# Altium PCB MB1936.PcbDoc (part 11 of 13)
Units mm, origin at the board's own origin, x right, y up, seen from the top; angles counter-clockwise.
Board outline 172 x 137 mm, 6 copper layers (Top Layer, Signal Layer 1, Signal Layer 2, Signal Layer 3, Signal Layer 4, Bottom Layer), stack 1.549 mm thick; 859 components, 672 nets, 3477 pads, 2222 vias.
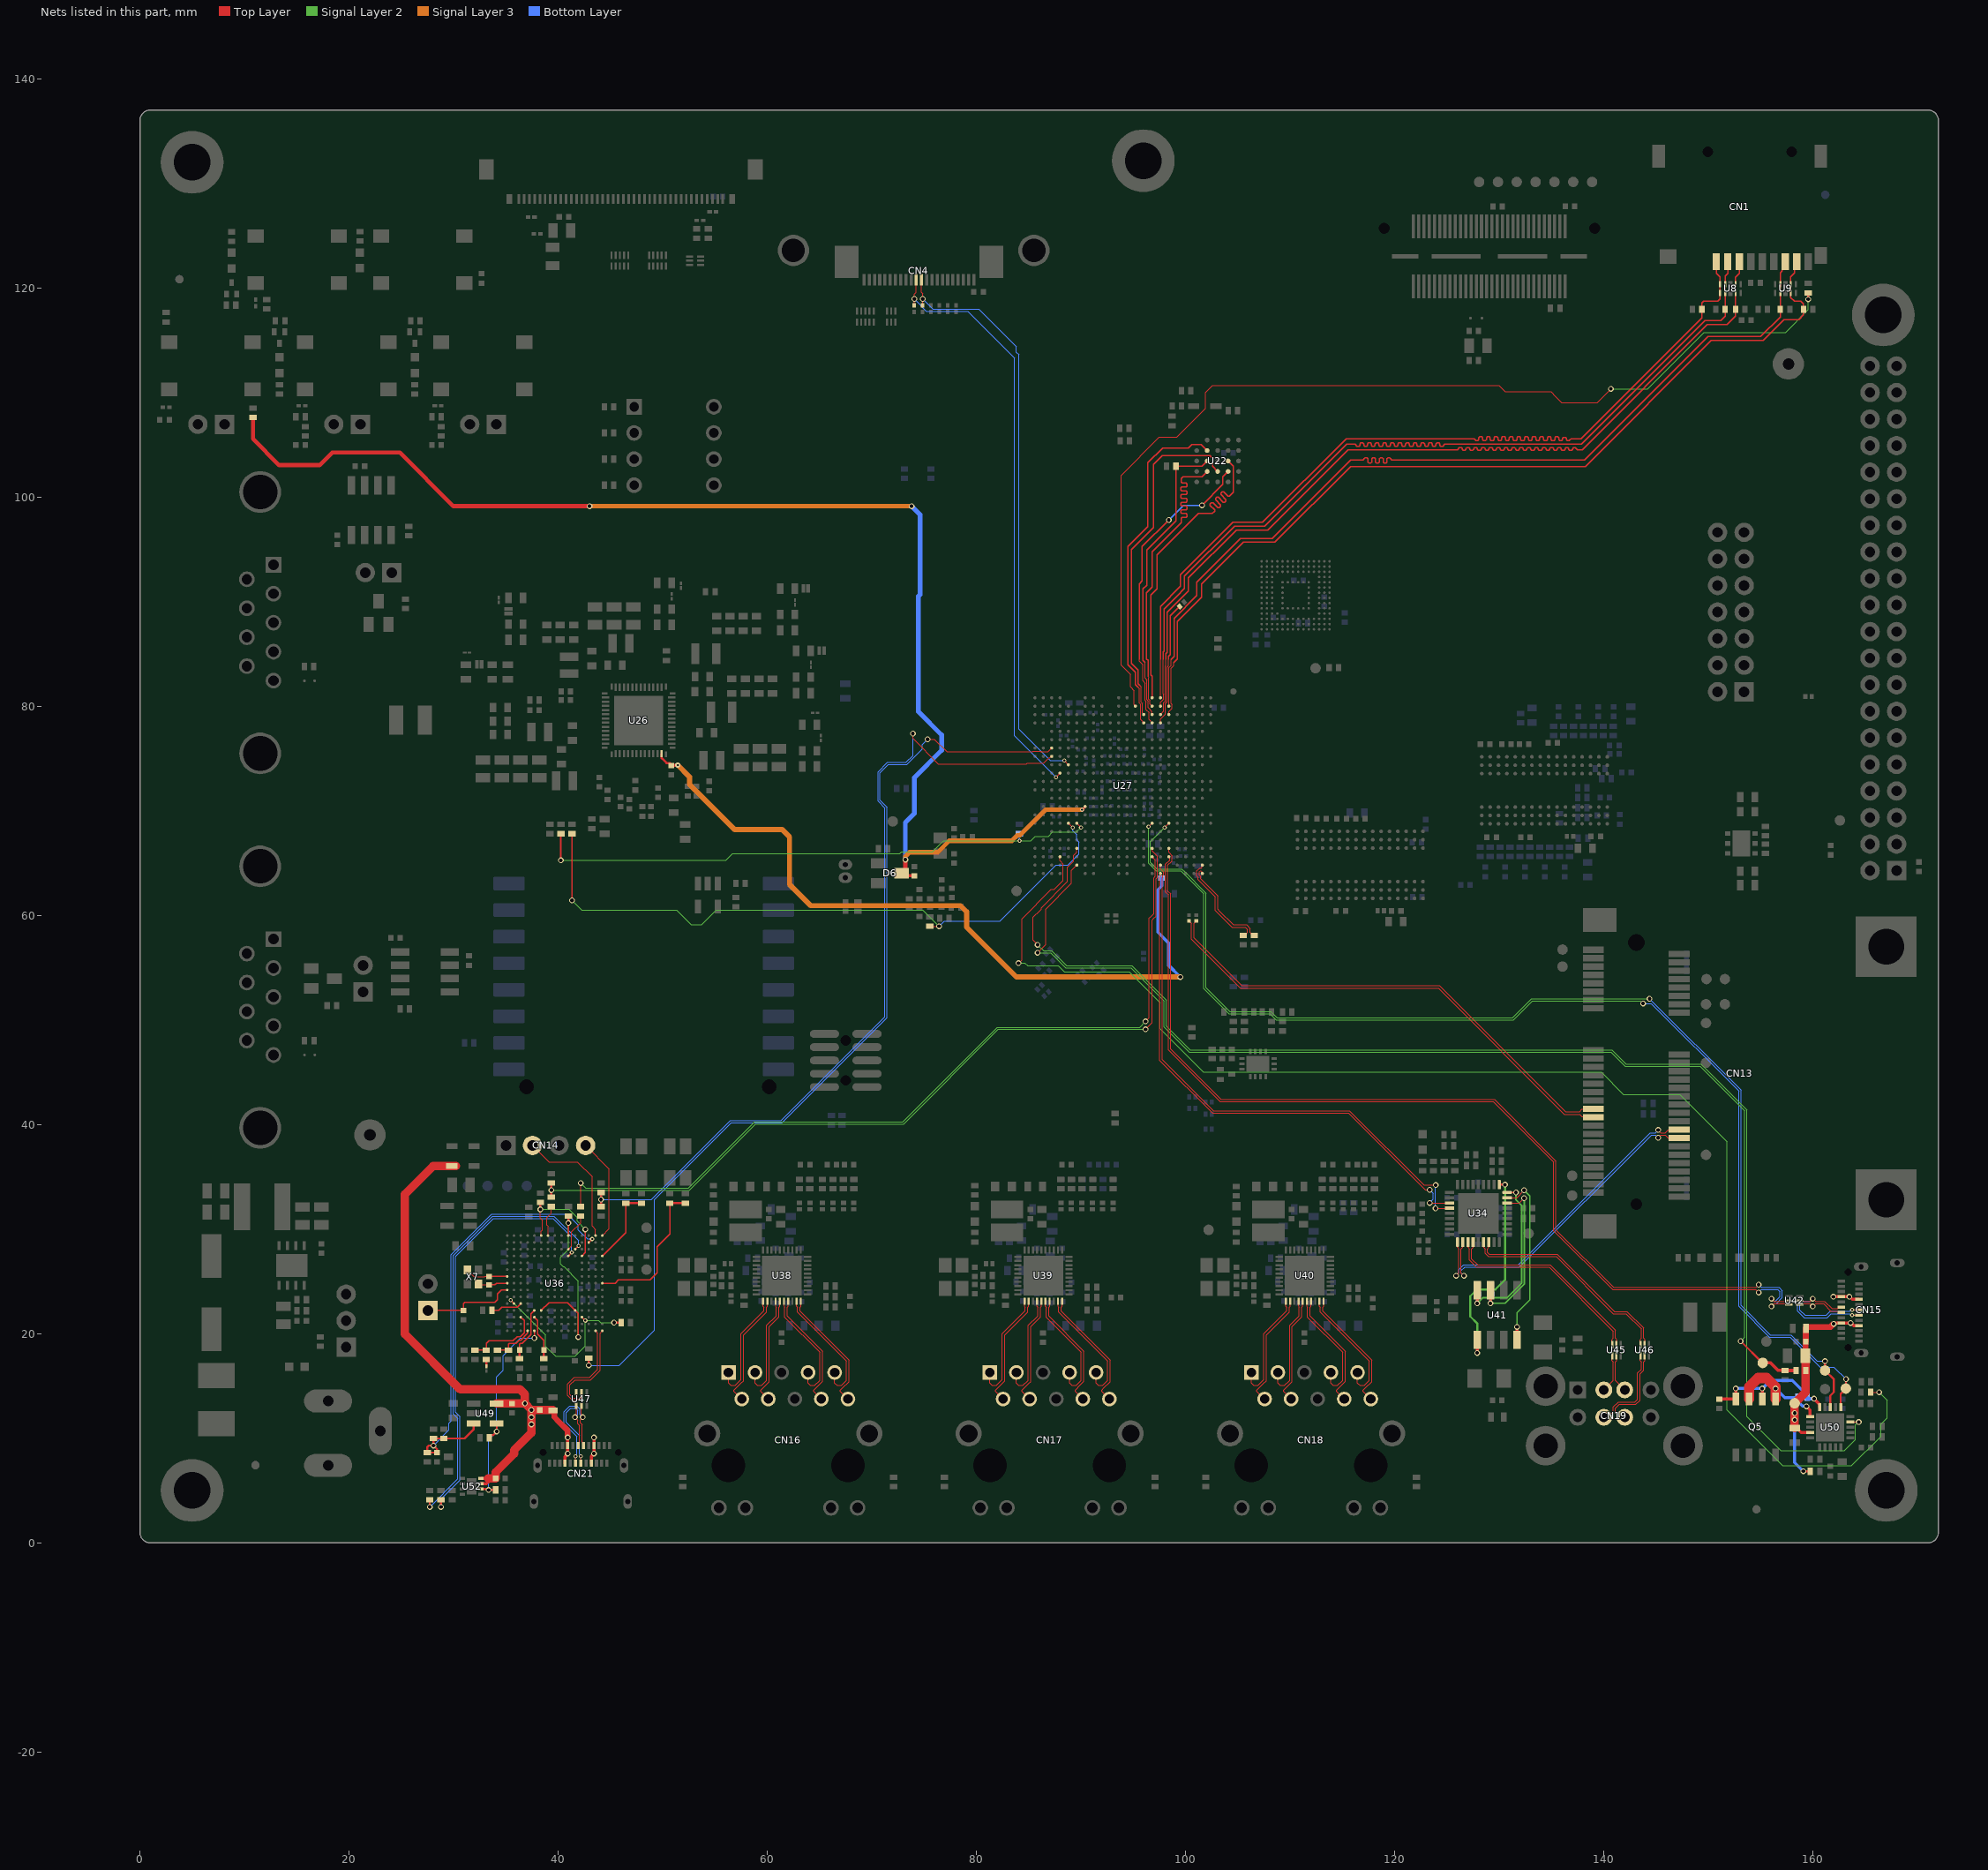
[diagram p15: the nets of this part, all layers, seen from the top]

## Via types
v1: diameter 0.55, hole 0.35, Top Layer to Bottom Layer, 1661 vias
v2: diameter 0.4, hole 0.2, Top Layer to Bottom Layer, tented both sides, 253 vias
v3: diameter 0.5, hole 0.2, Top Layer to Bottom Layer, 157 vias
v4: diameter 0.5, hole 0.25, Top Layer to Bottom Layer, 145 vias
v5: diameter 0.4, hole 0.2, Top Layer to Bottom Layer, 6 vias

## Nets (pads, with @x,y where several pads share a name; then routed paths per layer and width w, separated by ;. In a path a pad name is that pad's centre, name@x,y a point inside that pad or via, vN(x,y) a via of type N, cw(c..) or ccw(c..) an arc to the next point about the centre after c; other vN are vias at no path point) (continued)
PCIE.TX1_N: C98.2 CN13.31 | length 46.9
  Top Layer w0.09: C98.2@101.025,59.45 100.8,59.225 100.8,58.84 100.8,57.825 105.35,53.275 124.275,53.275 136.325,41.225 137.68,41.225 137.918,41.463 138.963,41.463 CN13.31@139,41.5
PCIE.TX1_P: C97.2 CN13.33 | length 47.3
  Top Layer w0.09: C97.2@100.325,59.45 100.55,59.225 100.55,58.84 100.55,57.721 105.246,53.025 124.171,53.025 136.221,40.975 137.68,40.975 137.918,40.737 138.963,40.737 CN13.33@139,40.7
PCIE.USB_N: CN13.36 U34.1 | length 30.9
  Top Layer w0.1: v1(125.875,25.543) 125.918,25.543 126.14,25.765 126.14,28.11 126,28.25 U34.1@126,28.75 ; v1(145.2,39.475) 145.2,39.455 145.445,39.21 145.86,39.21 146.15,39.5 CN13.36@147.2,39.5
  Bottom Layer w0.1: v1(125.875,25.543) 126.14,25.808 126.14,26.106 126.609,26.575 131.82,26.575 144.455,39.21 144.935,39.21 v1(145.2,39.475)
PCIE.USB_P: CN13.38 U34.2 | length 30.5
  Top Layer w0.1: U34.2@126.5,28.75 126.5,28.25 126.36,28.11 126.36,25.765 126.582,25.543 v1(126.625,25.543) ; v1(145.2,38.725) 145.2,38.745 145.445,38.99 145.86,38.99 146.15,38.7 CN13.38@147.2,38.7
  Bottom Layer w0.1: v1(126.625,25.543) 126.36,25.808 126.36,26.015 126.7,26.355 129.75,26.355 131.175,26.355 131.911,26.355 144.546,38.99 144.935,38.99 v1(145.2,38.725)
PCIE_CLKOUT_N: R78.1 U27.AB21 | length 9.6
  Top Layer w0.09: U27.AB21@101.6,64 101.56,64.04 101.56,64.195 101.504,64.251 101.425,64.251 101.335,64.16 101.335,63.85 101.445,63.74 101.445,63.509 102,62.954 102.85,62.104 103.082,61.872 103.082,60.571 103.179,60.475 104.554,59.1 105.825,59.1 106.175,58.75 106.175,58.475 106.175,58.333 106.224,58.285 106.365,58.285 R78.1@106.575,58.075
PCIE_CLKOUT_P: R77.1 U27.AA21 | length 10
  Top Layer w0.09: U27.AA21@101.6,64.8 101.56,64.76 101.56,64.585 101.5,64.525 101.346,64.525 101.085,64.264 101.085,63.746 101.195,63.637 101.195,63.543 101.195,63.406 101.75,62.85 102.6,62 102.832,61.768 102.832,60.475 102.832,60.468 104.45,58.85 105.721,58.85 105.925,58.646 105.925,58.35 105.925,58.333 105.877,58.285 105.735,58.285 R77.1@105.525,58.075
PWR_CPU_ON: R60.1 R272.2 U27.T6 | length 54.9
  Top Layer w0.1: U27.T6@89.6,68.8 v2(90,68.4)
  Top Layer w0.15: v1(40.25,65.25) 40.25,67.775 R60.1@40.275,67.8
  Signal Layer 2 w0.1: v1(40.25,65.25) 56.041,65.25 56.691,65.9 72.665,65.9 72.838,66.073 75.798,66.073 76.85,67.125 81.172,67.125 v2(84.125,67.125) 85.182,67.125 85.623,67.566 86.891,67.566 87.275,67.95 89.55,67.95 v2(90,68.4)
  Bottom Layer w0.1: R272.2@84.1,67.8 84.125,67.775 v2(84.125,67.125)
PWR_ON: R61.1 R74.2 U27.T5 | length 64.1
  Top Layer w0.09: R74.2@75.55,58.95 v1(76.425,58.95)
  Top Layer w0.1: U27.T5@88.8,68.8 v2(89.2,68.4)
  Top Layer w0.15: v1(41.325,61.425) R61.1@41.325,67.8
  Signal Layer 2 w0.1: v1(41.325,61.425) 42.25,60.5 51.325,60.5 52.725,59.1 53.725,59.1 55.125,60.5 74.875,60.5 v1(76.425,58.95)
  Bottom Layer w0.1: v1(76.425,58.95) 76.925,59.45 82.251,59.45 83.276,60.475 87.601,64.8 88.761,64.8 89.805,65.844 89.805,67.006 89.6,67.211 89.6,67.696 89.2,68.095 v2(89.2,68.4)
QSPI1.CLK: U22.B2 U27.D14 | length 32.9
  Top Layer w0.09: 95.44,81.81 95.585,81.665 95.585,80.308 95.69,80.203 95.69,78.71 U27.D14@96,78.4
  Top Layer w0.11: 95.44,81.81 95.2,82.05 95.2,83.25 94.475,83.975 94.475,95.25 96.4,97.175 96.4,103.275 97.8,104.675 100.25,104.675 100.6,105.025 101.482,105.025 U22.B2@102.066,104.441
QSPI1.IO0: U22.D3 U27.C14 | length 32.8
  Top Layer w0.09: 95.63,81.97 95.765,81.835 95.765,80.383 95.87,80.278 95.87,79.361 96,79.231 U27.C14@96,79.2
  Top Layer w0.11: 95.63,81.97 95.45,82.15 95.45,83.468 94.825,84.093 94.825,84.475 94.825,94.975 96.925,97.075 96.925,103.107 97.768,103.95 102.35,103.95 102.575,103.725 102.575,102.932 U22.D3@103.066,102.441
QSPI1.IO1: U22.D2 U27.B15 | length 31
  Top Layer w0.09: 96.405,82.82 96.485,82.74 96.485,80.681 96.59,80.576 96.59,80.225 96.8,80.015 U27.B15@96.8,80
  Top Layer w0.11: 96.405,82.82 96.405,84.395 96.271,84.529 96.271,90.846 96.825,91.4 96.825,94.775 99.575,97.525 99.575,97.54 99.575,97.959 99.666,98.05 100.064,98.05 100.155,98.141 100.155,98.323 100.064,98.414 99.645,98.414 99.554,98.505 99.554,98.687 99.645,98.778 100.064,98.778 100.155,98.869 100.155,99.051 100.064,99.142 99.645,99.142 99.554,99.233 99.554,99.415 99.645,99.506 100.064,99.506 100.155,99.597 100.155,99.779 100.064,99.87 99.645,99.87 99.554,99.961 99.554,100.143 99.645,100.234 100.064,100.234 100.155,100.325 100.155,100.507 100.064,100.598 99.645,100.598 99.554,100.689 99.554,100.871 99.645,100.962 100.064,100.962 100.155,101.053 100.155,101.235 100.064,101.326 99.666,101.326 99.575,101.417 99.575,101.55 99.575,101.75 99.775,101.95 101.575,101.95 U22.D2@102.066,102.441
QSPI1.IO2: U22.C4 U27.A15 | length 31.3
  Top Layer w0.11: U27.A15@96.8,80.8 96.8,82.85 96.68,82.97 96.68,90.63 97.275,91.225 97.275,94.45 101.25,98.425 102.55,98.425 102.737,98.612 102.776,98.651 102.776,98.78 102.351,99.206 102.351,99.334 102.479,99.463 102.608,99.463 103.083,98.988 103.212,98.988 103.34,99.117 103.34,99.246 102.866,99.721 102.866,99.849 102.994,99.978 103.123,99.978 103.598,99.503 103.726,99.503 103.855,99.632 103.855,99.761 103.38,100.235 103.38,100.364 103.509,100.493 103.638,100.493 104.063,100.067 104.192,100.067 104.563,100.438 104.575,100.45 104.575,102.932 U22.C4@104.066,103.441
QSPI1.IO3: U22.D4 U27.D15 | length 29.1
  Top Layer w0.09: 95.9,82.425 96.125,82.2 96.125,80.532 96.23,80.427 96.23,79.663 96.49,79.403 96.49,78.8 96.49,78.71 U27.D15@96.8,78.4
  Top Layer w0.1: 95.575,84.475 95.575,84.3 95.9,83.975 95.9,82.425
  Top Layer w0.11: 95.575,84.475 95.575,91.689 95.85,91.964 95.85,95.25 v1@98.399,97.799 ; v1(101.575,99.2) 103.575,101.2 103.575,101.95 U22.D4@104.066,102.441
  Bottom Layer w0.11: v1(98.4,97.8) 99.8,99.2 v1(101.575,99.2)
QSPI1.NCS1: R33.1 U22.C2 U27.C15 | length 28.6
  Top Layer w0.09: 96.125,82.675 96.305,82.495 96.305,80.606 96.41,80.501 96.41,79.866 96.781,79.495 96.781,79.219 U27.C15@96.8,79.2
  Top Layer w0.1: 96.125,82.675 96.125,84.18
  Top Layer w0.11: 96.125,84.18 95.925,84.38 95.925,84.641 95.925,91.2 96.3,91.575 96.3,94.925 99.084,97.709 R33.1@99.084,102.95 101.575,102.95 U22.C2@102.066,103.441
RJ451_D1_N: CN17.2 U39.2 | length 11
  Top Layer w0.09: CN17.2@82.555,13.75 81.825,14.48 81.825,14.6 82.369,15.144 82.496,15.271 82.725,15.5 82.725,19.875 84.925,22.075 84.925,22.55 85,22.625 U39.2@85,23.1
RJ451_D1_P: CN17.1 U39.1 | length 11
  Top Layer w0.09: CN17.1@81.285,16.29 81.285,15.265 81.5,15.05 81.921,15.05 82.392,15.521 82.475,15.604 82.475,19.979 84.675,22.179 84.675,22.55 84.6,22.625 U39.1@84.6,23.1
RJ451_D2_N: CN17.4 U39.5 | length 10.4
  Top Layer w0.09: CN17.4@85.095,13.75 84.365,14.48 84.365,14.6 84.909,15.144 85.036,15.271 85.182,15.417 85.2,15.435 85.2,20.675 86.125,21.6 86.125,22.55 86.2,22.625 U39.5@86.2,23.1
RJ451_D2_P: CN17.3 U39.4 | length 10.4
  Top Layer w0.09: CN17.3@83.825,16.29 83.825,15.265 84.04,15.05 84.461,15.05 84.95,15.539 84.95,20.779 85.875,21.704 85.875,22.55 85.8,22.625 U39.4@85.8,23.1
RJ451_D3_N: CN17.8 U39.7 | length 11.4
  Top Layer w0.09: U39.7@87,23.1 87,22.625 86.925,22.55 86.925,21.679 90.275,18.329 90.275,15.43 89.989,15.144 89.445,14.6 89.445,14.48 CN17.8@90.175,13.75
RJ451_D3_P: CN17.7 U39.6 | length 11.4
  Top Layer w0.09: U39.6@86.6,23.1 86.6,22.625 86.675,22.55 86.675,21.575 90.025,18.225 90.025,15.534 89.541,15.05 89.12,15.05 88.905,15.265 CN17.7@88.905,16.29
RJ451_D4_N: CN17.10 U39.10 | length 12
  Top Layer w0.09: U39.10@88.2,23.1 88.2,22.625 88.125,22.55 88.125,22.154 91.625,18.654 92.802,17.476 92.802,15.417 92.221,14.836 91.985,14.6 91.985,14.48 CN17.10@92.715,13.75
RJ451_D4_P: CN17.9 U39.9 | length 12
  Top Layer w0.09: U39.9@87.8,23.1 87.8,22.625 87.875,22.55 87.875,22.05 92.552,17.373 92.552,15.521 92.081,15.05 91.66,15.05 91.445,15.265 CN17.9@91.445,16.29
RJ452_D1_N: CN16.2 U38.2 | length 11
  Top Layer w0.09: CN16.2@57.555,13.75 56.825,14.48 56.825,14.6 57.369,15.144 57.496,15.271 57.725,15.5 57.725,19.875 59.925,22.075 59.925,22.55 60,22.625 U38.2@60,23.1
RJ452_D1_P: CN16.1 U38.1 | length 11
  Top Layer w0.09: CN16.1@56.285,16.29 56.285,15.265 56.5,15.05 56.921,15.05 57.392,15.521 57.475,15.604 57.475,19.979 59.675,22.179 59.675,22.55 59.6,22.625 U38.1@59.6,23.1
RJ452_D2_N: CN16.4 U38.5 | length 10.4
  Top Layer w0.09: CN16.4@60.095,13.75 59.365,14.48 59.365,14.6 59.909,15.144 60.036,15.271 60.182,15.417 60.2,15.435 60.2,20.675 61.125,21.6 61.125,22.55 61.2,22.625 U38.5@61.2,23.1
RJ452_D2_P: CN16.3 U38.4 | length 10.4
  Top Layer w0.09: CN16.3@58.825,16.29 58.825,15.265 59.04,15.05 59.461,15.05 59.95,15.539 59.95,20.779 60.875,21.704 60.875,22.55 60.8,22.625 U38.4@60.8,23.1
RJ452_D3_N: CN16.8 U38.7 | length 11.4
  Top Layer w0.09: U38.7@62,23.1 62,22.625 61.925,22.55 61.925,21.679 65.275,18.329 65.275,15.43 64.989,15.144 64.445,14.6 64.445,14.48 CN16.8@65.175,13.75
RJ452_D3_P: CN16.7 U38.6 | length 11.4
  Top Layer w0.09: U38.6@61.6,23.1 61.6,22.625 61.675,22.55 61.675,21.575 65.025,18.225 65.025,15.534 64.541,15.05 64.12,15.05 63.905,15.265 CN16.7@63.905,16.29
RJ452_D4_N: CN16.10 U38.10 | length 12
  Top Layer w0.09: U38.10@63.2,23.1 63.2,22.625 63.125,22.55 63.125,22.154 66.625,18.654 67.802,17.476 67.802,15.417 67.221,14.836 66.985,14.6 66.985,14.48 CN16.10@67.715,13.75
RJ452_D4_P: CN16.9 U38.9 | length 12
  Top Layer w0.09: U38.9@62.8,23.1 62.8,22.625 62.875,22.55 62.875,22.05 67.552,17.373 67.552,15.521 67.081,15.05 66.66,15.05 66.445,15.265 CN16.9@66.445,16.29
RJ453_D1_N: CN18.2 U40.2 | length 11
  Top Layer w0.09: CN18.2@107.555,13.75 106.825,14.48 106.825,14.6 107.369,15.144 107.496,15.271 107.725,15.5 107.725,19.875 109.925,22.075 109.925,22.55 110,22.625 U40.2@110,23.1
RJ453_D1_P: CN18.1 U40.1 | length 11
  Top Layer w0.09: CN18.1@106.285,16.29 106.285,15.265 106.5,15.05 106.921,15.05 107.392,15.521 107.475,15.604 107.475,19.979 109.675,22.179 109.675,22.55 109.6,22.625 U40.1@109.6,23.1
RJ453_D2_N: CN18.4 U40.5 | length 10.4
  Top Layer w0.09: CN18.4@110.095,13.75 109.365,14.48 109.365,14.6 109.909,15.144 110.036,15.271 110.182,15.417 110.2,15.435 110.2,20.675 111.125,21.6 111.125,22.55 111.2,22.625 U40.5@111.2,23.1
RJ453_D2_P: CN18.3 U40.4 | length 10.4
  Top Layer w0.09: CN18.3@108.825,16.29 108.825,15.265 109.04,15.05 109.461,15.05 109.95,15.539 109.95,20.779 110.875,21.704 110.875,22.55 110.8,22.625 U40.4@110.8,23.1
RJ453_D3_N: CN18.8 U40.7 | length 11.4
  Top Layer w0.09: U40.7@112,23.1 112,22.625 111.925,22.55 111.925,21.679 115.275,18.329 115.275,15.43 114.989,15.144 114.445,14.6 114.445,14.48 CN18.8@115.175,13.75
RJ453_D3_P: CN18.7 U40.6 | length 11.4
  Top Layer w0.09: U40.6@111.6,23.1 111.6,22.625 111.675,22.55 111.675,21.575 115.025,18.225 115.025,15.534 114.541,15.05 114.12,15.05 113.905,15.265 CN18.7@113.905,16.29
RJ453_D4_N: CN18.10 U40.10 | length 12
  Top Layer w0.09: U40.10@113.2,23.1 113.2,22.625 113.125,22.55 113.125,22.154 116.625,18.654 117.802,17.476 117.802,15.417 117.221,14.836 116.985,14.6 116.985,14.48 CN18.10@117.715,13.75
RJ453_D4_P: CN18.9 U40.9 | length 12
  Top Layer w0.09: U40.9@112.8,23.1 112.8,22.625 112.875,22.55 112.875,22.05 117.552,17.373 117.552,15.521 117.081,15.05 116.66,15.05 116.445,15.265 CN18.9@116.445,16.29
SD.SDMMC1_CK: R247.1 U27.D16 | length 11.9
  Top Layer w0.09: 97.6,78.762 98.09,79.252 98.09,80.244 98.245,80.399 98.245,83.761 98.369,83.885 98.369,84.475
  Top Layer w0.1: U27.D16@97.6,78.4 97.6,78.762
  Top Layer w0.11: 98.369,84.475 98.369,84.744 98.55,84.925 98.55,88.65 R247.1@99.438,89.538
SD.SDMMC1_CMD: CN1.3 R12.1 U8.4 U8.7 U27.C16 | length 86.1
  Top Layer w0.09: U27.C16@97.6,79.2 97.91,79.51 97.91,80.319 98.065,80.474 98.065,83.836 98.115,83.886 98.115,84.475
  Top Layer w0.11: 98.115,84.475 98.115,85.015 98.237,85.138 98.237,88.962 100.285,91.01 100.285,92.26 104.846,96.82 107.845,96.82 115.525,104.5 125.946,104.5 126.001,104.5 126.092,104.591 126.092,104.614 126.183,104.705 126.365,104.705 126.456,104.614 126.456,104.567 126.547,104.476 126.729,104.476 126.82,104.567 126.82,104.614 126.911,104.705 127.093,104.705 127.184,104.614 127.184,104.567 127.275,104.476 127.457,104.476 127.548,104.567 127.548,104.614 127.639,104.705 127.821,104.705 127.912,104.614 127.912,104.567 128.003,104.476 128.185,104.476 128.276,104.567 128.276,104.614 128.367,104.705 128.549,104.705 128.64,104.614 128.64,104.567 128.731,104.476 128.913,104.476 129.004,104.567 129.004,104.614 129.095,104.705 129.277,104.705 129.368,104.614 129.368,104.567 129.459,104.476 129.641,104.476 129.732,104.567 129.732,104.614 129.823,104.705 130.005,104.705 130.096,104.614 130.096,104.567 130.187,104.476 130.369,104.476 130.46,104.567 130.46,104.614 130.551,104.705 130.733,104.705 130.824,104.614 130.824,104.567 130.915,104.476 131.097,104.476 131.188,104.567 131.188,104.614 131.279,104.705 131.461,104.705 131.552,104.614 131.552,104.567 131.643,104.476 131.825,104.476 131.916,104.567 131.916,104.614 132.007,104.705 132.189,104.705 132.28,104.614 132.28,104.567 132.371,104.476 132.553,104.476 132.644,104.567 132.644,104.614 132.735,104.705 132.917,104.705 133.008,104.614 133.008,104.567 133.099,104.476 133.281,104.476 133.372,104.567 133.372,104.614 133.463,104.705 133.645,104.705 133.736,104.614 133.736,104.567 133.827,104.476 134.009,104.476 134.1,104.567 134.1,104.614 134.191,104.705 134.373,104.705 134.464,104.614 134.464,104.567 134.555,104.476 134.737,104.476 134.828,104.567 134.828,104.614 134.919,104.705 135.101,104.705 135.192,104.614 135.192,104.567 135.283,104.476 135.465,104.476 135.556,104.567 135.556,104.614 135.647,104.705 135.829,104.705 135.92,104.614 135.92,104.567 136.011,104.476 136.193,104.476 136.284,104.567 136.284,104.614 136.375,104.705 136.557,104.705 136.648,104.614 136.648,104.567 136.739,104.476 136.921,104.476 137.012,104.567 137.012,104.611 137.103,104.702 137.285,104.702 137.376,104.611 137.376,104.591 137.467,104.5 137.7,104.5 137.925,104.5 149.9,116.475 151.8,116.475 152.6,117.275 R12.1@152.6,117.95 U8.4@152.6,119.52 U8.7@152.6,120.34 152.6,121.02 152.95,121.37 CN1.3@152.95,122.5
SD.SDMMC1_D0: CN1.7 R14.1 U9.2 U9.9 U27.B17 | length 87.4
  Top Layer w0.09: U27.B17@98.4,80 98.4,80.3 98.425,80.325 98.425,83.687 98.623,83.885 98.623,84.473
  Top Layer w0.11: 98.625,84.475 98.9,84.75 98.9,88.4 101.081,90.581 101.081,91.856 105.25,96.025 108.3,96.025 115.8,103.525 116.913,103.525 116.968,103.525 117.077,103.634 117.077,103.649 117.186,103.758 117.332,103.758 117.441,103.649 117.441,103.331 117.55,103.222 117.696,103.222 117.805,103.331 117.805,103.649 117.914,103.758 118.06,103.758 118.169,103.649 118.169,103.331 118.278,103.222 118.424,103.222 118.533,103.331 118.533,103.649 118.642,103.758 118.788,103.758 118.897,103.649 118.897,103.331 119.006,103.222 119.152,103.222 119.261,103.331 119.261,103.649 119.37,103.758 119.516,103.758 119.625,103.649 119.625,103.634 119.734,103.525 120.062,103.525 138.15,103.525 149.975,115.35 155.005,115.35 156.875,117.22 R14.1@156.875,117.95 U9.2@156.875,119.52 U9.9@156.875,120.34 156.875,121.425 157.068,121.618 157.068,122.218 CN1.7@157.35,122.5
SD.SDMMC1_D1: CN1.8 R15.1 U9.4 U9.7 U27.C17 | length 88.3
  Top Layer w0.09: U27.C17@98.4,79.2 98.4,79.5 98.685,79.785 98.685,80.156 98.605,80.236 98.605,83.612 98.877,83.884 98.877,84.18
  Top Layer w0.11: 98.877,84.18 99.225,84.527 99.225,88.1 101.525,90.4 101.525,91.675 105.55,95.7 108.55,95.7 115.775,102.925 138.225,102.925 150.275,114.975 155.25,114.975 157.225,116.95 158.65,116.95 159.1,117.4 R15.1@159.1,117.95 159.1,118.47 158.845,118.725 158.225,118.725 157.875,119.075 U9.4@157.875,119.52 U9.7@157.875,120.34 157.875,121.045 158.25,121.42 158.25,122.3 CN1.8@158.45,122.5
SD.SDMMC1_D2: CN1.1 R10.1 U8.1 U8.10 U27.A16 | length 86.1
  Top Layer w0.09: U27.A16@97.6,80.8 97.6,84.475
  Top Layer w0.11: 97.6,84.475 97.6,89.525 99.525,91.45 99.525,92.575 104.531,97.581 107.356,97.581 115.35,105.575 127.17,105.575 127.589,105.575 127.68,105.484 127.68,105.471 127.771,105.38 127.953,105.38 128.044,105.471 128.044,105.665 128.135,105.756 128.317,105.756 128.408,105.665 128.408,105.471 128.499,105.38 128.681,105.38 128.772,105.471 128.772,105.665 128.863,105.756 129.045,105.756 129.136,105.665 129.136,105.471 129.227,105.38 129.409,105.38 129.5,105.471 129.5,105.665 129.591,105.756 129.773,105.756 129.864,105.665 129.864,105.471 129.955,105.38 130.137,105.38 130.228,105.471 130.228,105.665 130.319,105.756 130.501,105.756 130.592,105.665 130.592,105.471 130.683,105.38 130.865,105.38 130.956,105.471 130.956,105.665 131.047,105.756 131.229,105.756 131.32,105.665 131.32,105.471 131.411,105.38 131.593,105.38 131.684,105.471 131.684,105.665 131.775,105.756 131.957,105.756 132.048,105.665 132.048,105.471 132.139,105.38 132.321,105.38 132.412,105.471 132.412,105.665 132.503,105.756 132.685,105.756 132.776,105.665 132.776,105.471 132.867,105.38 133.049,105.38 133.14,105.471 133.14,105.665 133.231,105.756 133.413,105.756 133.504,105.665 133.504,105.471 133.595,105.38 133.777,105.38 133.868,105.471 133.868,105.665 133.959,105.756 134.141,105.756 134.232,105.665 134.232,105.471 134.323,105.38 134.505,105.38 134.596,105.471 134.596,105.665 134.687,105.756 134.869,105.756 134.96,105.665 134.96,105.471 135.051,105.38 135.233,105.38 135.324,105.471 135.324,105.665 135.415,105.756 135.597,105.756 135.688,105.665 135.688,105.471 135.779,105.38 135.961,105.38 136.052,105.471 136.052,105.588 136.143,105.679 136.325,105.679 136.416,105.588 136.416,105.484 136.507,105.393 136.689,105.393 136.78,105.484 136.871,105.575 137.65,105.575 137.825,105.575 149.375,117.125 R10.1@149.375,117.95 149.375,118.55 149.55,118.725 150.885,118.725 151.1,118.94 U8.1@151.1,119.52 U8.10@151.1,120.34 151.1,121.04 150.75,121.39 CN1.1@150.75,122.5
SD.SDMMC1_D3: CN1.2 R11.1 U8.2 U8.9 U27.B16 | length 86.1
  Top Layer w0.09: U27.B16@97.6,80 97.6,80.365 97.805,80.57 97.805,80.574 97.885,80.654 97.885,81.151 97.861,81.175 97.861,84.475
  Top Layer w0.11: 97.861,84.475 97.861,85.186 97.938,85.262 97.938,89.284 99.15,90.496 99.896,91.242 99.896,92.421 104.684,97.209 107.584,97.209 115.425,105.05 115.8,105.05 116.219,105.05 116.31,104.959 116.31,104.917 116.401,104.826 116.583,104.826 116.674,104.917 116.674,105.074 116.765,105.165 116.947,105.165 117.038,105.074 117.038,104.917 117.129,104.826 117.311,104.826 117.402,104.917 117.402,105.074 117.493,105.165 117.675,105.165 117.766,105.074 117.766,104.917 117.857,104.826 118.039,104.826 118.13,104.917 118.13,105.074 118.221,105.165 118.403,105.165 118.494,105.074 118.494,104.917 118.585,104.826 118.767,104.826 118.858,104.917 118.858,105.074 118.949,105.165 119.131,105.165 119.222,105.074 119.222,104.917 119.313,104.826 119.495,104.826 119.586,104.917 119.586,105.074 119.677,105.165 119.859,105.165 119.95,105.074 119.95,104.917 120.041,104.826 120.223,104.826 120.314,104.917 120.314,105.074 120.405,105.165 120.587,105.165 120.678,105.074 120.678,104.917 120.769,104.826 120.951,104.826 121.042,104.917 121.042,105.074 121.133,105.165 121.315,105.165 121.406,105.074 121.406,104.917 121.497,104.826 121.679,104.826 121.77,104.917 121.77,105.074 121.861,105.165 122.043,105.165 122.134,105.074 122.134,104.917 122.225,104.826 122.407,104.826 122.498,104.917 122.498,105.074 122.589,105.165 122.771,105.165 122.862,105.074 122.862,104.917 122.953,104.826 123.135,104.826 123.226,104.917 123.226,105.074 123.317,105.165 123.499,105.165 123.59,105.074 123.59,104.917 123.681,104.826 123.863,104.826 123.954,104.917 123.954,105.074 124.045,105.165 124.227,105.165 124.318,105.074 124.318,104.928 124.409,104.837 124.591,104.837 124.682,104.928 124.682,104.959 124.773,105.05 125.7,105.05 137.85,105.05 149.675,116.875 151.2,116.875 151.6,117.275 R11.1@151.6,117.95 U8.2@151.6,119.52 U8.9@151.6,120.34 151.6,121.128 151.85,121.378 CN1.2@151.85,122.5
SD.uSD_DETECT: R6.1 U27.B13 | length 98.8
  Top Layer w0.09: 93.85,84.475 93.85,83.92 94.745,83.025 94.745,81.835 95.095,81.485 95.095,80.158 95.2,80.053 U27.B13@95.2,80
  Top Layer w0.1: 93.85,84.475 93.85,102.078 97.497,105.725 99.165,105.725 101.9,108.46 101.9,110 102.575,110.675 129.96,110.675 130.575,110.06 134.929,110.06 135.378,109.611 ; 135.371,109.604 135.94,109.035 139.36,109.035 v1(140.675,110.35)
  Top Layer w0.2: v1(159.55,118.905) R6.1@159.55,119.525
  Signal Layer 2 w0.1: v1(140.675,110.35) 144.2,110.35 149.6,115.75 157.375,115.75 159.55,117.925 v1(159.55,118.905)
SRC_GDPG: C162.1 Q5.2 Q5.4 R325.2 U50.5 | length 13.2
  Top Layer w0.2: Q5.2@155.15,13.755 Q5.2@155.155,13.75
  Top Layer w0.3: C162.1@151.045,13.75 Q5.4@152.615,13.75 ; Q5.4@152.61,13.755 v1(152.61,14.75) ; Q5.2@155.15,13.755 v1(155.15,14.75) ; v1(160.1,13.775) 160.65,13.225 U50.5@160.65,12.975
  Bottom Layer w0.3: v1(152.61,14.75) v1(155.15,14.75) 155.925,15.525 158.025,15.525 159.345,14.205 159.345,14.03 R325.2@159.45,13.925 ; R325.2@159.401,13.775 v1(160.1,13.775)
SRC_GDPS: Q5.1 Q5.3 R325.1 U50.6 | length 11.6
  Top Layer w0.3: Q5.1@156.42,13.755 v1(156.42,14.75) ; v1(159.375,13.05) 159.725,12.7 U50.6@159.725,12.05
  Top Layer w1: Q5.3@153.885,13.75 153.885,14.9 154.741,15.756 155.569,15.756 156.425,14.9 Q5.1@156.425,13.75
  Bottom Layer w0.3: v1(156.42,14.75) 157.295,13.875 R325.1@158.55,13.875 ; R325.1@158.55,13.925 158.655,13.82 158.655,13.41 158.982,13.082 159.343,13.082 v1(159.375,13.05)
STLK_LED: R130.1 R131.2 U36.D15 | length 7.5
  Top Layer w0.12: U36.D15@44.225,27.425 46.475,29.675 R130.1@46.475,32.475
  Top Layer w0.2: R130.1@46.475,32.475 R131.2@47.975,32.475
STLK_NRST: C149.2 JP3.1 U36.J1 | length 9
  Top Layer w0.12: JP3.1@27.597,22.225 C149.2@30.95,22.225 30.95,22.879 31.071,23 33.93,23 34.185,23.255 34.185,23.775 34.585,24.175 U36.J1@35.125,24.175
STLK_OSC_IN: C133.1 U36.G1 X7.1 | length 4.1
  Top Layer w0.1: X7.1@31.325,26.1 31.325,26.05 31.95,25.425 32.95,25.425 33,25.475 C133.1@33.395,25.475
  Top Layer w0.12: C133.1@33.395,25.475 U36.G1@35.125,25.475
STLK_OSC_OUT: C140.2 U36.H1 X7.3 | length 2.8
  Top Layer w0.1: X7.3@32.375,24.75 32.45,24.675 C140.2@33.395,24.675
  Top Layer w0.12: C140.2@33.395,24.675 33.95,24.675 34.1,24.825 U36.H1@35.125,24.825
STLK_SWCLK: CN14.2 U36.A14 | length 12.7
  Top Layer w0.1: CN14.2@37.545,38 39.145,36.4 41.85,36.4 43.25,35 43.25,30.3 43.575,29.975 U36.A14@43.575,29.375
STLK_SWDIO: CN14.4 U36.A15 | length 9.8
  Top Layer w0.1: CN14.4@42.625,38 44.875,35.75 44.875,30.025 U36.A15@44.225,29.375
STLK_UCPD_CC1_C: C157.1 R217.1 U36.M5 | length 5.3
  Top Layer w0.12: 36.568,19.068 37.4,19.9 37.4,21.9 U36.M5@37.725,22.225
  Top Layer w0.125: C157.1@36.305,18.425 36.305,18.994 36.378,19.068 36.568,19.068
  Top Layer w0.2: R217.1@36.305,17.6 C157.1@36.305,18.425
STLK_UCPD_CC2_C: C158.1 R218.1 U36.N5 | length 4.3
  Top Layer w0.12: U36.N5@37.725,21.575 38.05,21.25 38.05,19.95 38.625,19.375 C158.1@38.625,18.425
  Top Layer w0.2: R218.1@38.625,17.6 C158.1@38.625,18.425
STLK_USB_CN_N: CN21.A7 CN21.B7 U47.2 | length 12.3
  Top Layer w0.1: CN21.B7@41.665,7.61 v5(41.665,8.27) ; U47.2@42.225,13.114 42.225,12.139 v1(42.35,12.014) 42.11,11.774 42.11,11.49 42.275,11.325 42.275,9.65 42.415,9.51 CN21.A7@42.415,9.31
  Bottom Layer w0.1: v5(41.665,8.27) 41.665,8.339 41.805,8.479 41.805,10.161 40.555,11.411 40.555,12.53 41.1,13.075 41.775,13.075 42.085,12.765 42.085,12.267 42.338,12.014 v1(42.35,12.014)
STLK_USB_CN_P: CN21.A6 CN21.B6 U47.1 | length 11.6
  Top Layer w0.1: U47.1@41.725,13.114 41.725,12.139 v1(41.6,12.014) 41.89,11.724 41.89,11.465 41.89,11.399 42.055,11.234 42.055,9.65 41.915,9.51 CN21.A6@41.915,9.31 ; CN21.B6@42.165,7.61 v5(42.165,8.27)
  Bottom Layer w0.1: v1(41.6,12.014) 41.612,12.014 41.865,12.267 41.865,12.674 41.684,12.855 41.191,12.855 40.775,12.439 40.775,11.503 42.025,10.253 42.025,8.479 42.165,8.339 v5(42.165,8.27)
STLK_USB_N: U36.R14 U47.5 | length 10.5
  Top Layer w0.1: U47.5@42.225,14.414 42.225,13.889 42.091,13.755 41.883,13.755 41.758,13.63 41.359,13.63 40.905,14.084 40.905,15.18 41.525,15.8 43,15.8 43.79,16.59 43.79,20.06 U36.R14@43.575,20.275
STLK_USB_P: U36.R15 U47.6 | length 9.5
  Top Layer w0.1: U47.6@41.725,14.414 41.725,13.909 41.666,13.85 41.45,13.85 41.125,14.175 41.125,15.089 41.616,15.58 41.774,15.58 43.008,15.58 43.091,15.58 44.01,16.499 44.01,20.06 U36.R15@44.225,20.275
STLK_VCP_RX: R154.1 U36.C10 | length 3.7
  Top Layer w0.1: U36.C10@40.975,28.075 41.3,28.4 41.3,29.737 42.15,30.587 R154.1@42.15,31.25
STLK_VCP_TX: R134.1 U36.A7 | length 3
  Top Layer w0.1: U36.A7@39.025,29.375 39.025,30.274 38.925,30.374 38.925,31.08 39.35,31.505 R134.1@39.35,32.15
T_JTDI: R207.1 U36.L3 | length 3
  Top Layer w0.12: R207.1@33.675,22.225 34.3,22.225 34.625,22.55 36.1,22.55 U36.L3@36.425,22.875
T_PWR_EN: R229.2 R239.2 U36.R5 U49.4 U52.2 | length 21
  Top Layer w0.12: v1(37.725,19.575) U36.R5@37.725,20.275
  Top Layer w0.2: U52.2@32.625,5.15 v1@33.35,5.15 ; v1(33.35,5.05) R239.2@34.025,5.05 ; R229.2@33.425,10.05 33.425,10.145 33.58,10.3 33.78,10.3 v1(34.125,10.645) U49.4@34.125,11.425
  Bottom Layer w0.1: v1(33.35,5.05) 33.35,9.87 v1(34.125,10.645) 34.125,15.875 34.725,16.475 34.725,17.9 36.4,19.575 v1(37.725,19.575)
T_PWR_EXT: R215.1 R216.1 U36.R4 | length 4.1
  Top Layer w0.12: R215.1@34.2,18.425 R216.1@35.25,18.425 35.25,18.975 35.342,19.068 35.955,19.068 36.262,19.375 36.425,19.375 37.075,20.025 U36.R4@37.075,20.275
T_PWR_INT: C176.2 R226.1 R227.2 R230.2 U36.B13 U49.3 | length 44.1
  Top Layer w0.15: U36.B13@42.925,28.725 v2(43.25,29.05)
  Top Layer w0.2: U49.3@31.925,11.425 31.925,10.854 31.046,9.975 R226.1@28.07,9.975 v1(28.07,9.3) ; v1(28.07,9.3) 27.637,9.3 27.475,9.138 R230.2@27.475,8.625 C176.2@28.425,8.625 28.425,8.945 v1(28.07,9.3)
  Bottom Layer w0.1: v1(28.07,9.3) 29.55,10.78 29.55,11.426 29.775,11.651 29.775,27.541 33.659,31.425 40.867,31.425 41.931,30.361 41.931,29.919 42.8,29.05 v2(43.25,29.05)
T_PWR_LED: R132.2 R133.2 U36.H15 | length 14.3
  Top Layer w0.12: U36.H15@44.225,24.825 45.445,24.825 45.77,25.15 48.775,25.15 49.45,25.825 49.45,28.293 50.675,29.518 R132.2@50.675,32.475
  Top Layer w0.2: R132.2@50.675,32.475 R133.2@52.175,32.475
T_PWR_SEL1: R241.2 U36.D10 | length 40.9
  Top Layer w0.15: U36.D10@40.975,27.425 v2(41.3,27.75)
  Top Layer w0.2: v1(28.795,3.425) R241.2@28.795,4.1
  Bottom Layer w0.1: v1(28.795,3.425) 28.795,4.195 30.6,6 30.6,12.049 30.175,12.474 30.175,27.375 33.825,31.025 39.526,31.025 41.3,29.251 v2(41.3,27.75)
T_PWR_SEL2: R240.2 U36.C11 | length 41.4
  Top Layer w0.15: U36.C11@41.625,28.075 v2(41.95,28.4)
  Top Layer w0.2: v1(27.72,3.425) R240.2@27.72,4.1
  Bottom Layer w0.1: v1(27.72,3.425) 30.4,6.105 30.4,11.9 29.975,12.325 29.975,27.458 33.742,31.225 39.609,31.225 41.95,28.884 v2(41.95,28.4)
T_SWCLK: R153.1 U36.A10 U36.M6 U36.M11 | length 20.4
  Top Layer w0.12: U36.M6@38.375,22.225 39.113,22.963 40.887,22.963 U36.M11@41.625,22.225 41.925,21.925 v1(41.925,19.675) ; U36.A10@40.975,29.375 v1(40.975,30.575)
  Top Layer w0.2: v1(40.975,30.575) R153.1@40.975,31.25
  Signal Layer 2 w0.1: v1(40.975,30.575) 40.975,28.075 40.215,27.315 40.215,26.645 40.47,26.39 40.569,26.39 41.925,25.034 v1(41.925,19.675)
T_SWDIO: R209.1 U36.L2 U36.N12 | length 17.3
  Top Layer w0.15: v2(35.45,23.2) U36.L2@35.775,22.875 ; U36.N12@42.275,21.575 v2(42.6,21.25)
  Top Layer w0.2: v1(45.35,21.05) R209.1@46.025,21.05
  Signal Layer 2 w0.1: v2(35.45,23.2) 38.8,19.85 38.8,18.775 39.75,17.825 41.625,17.825 42.6,18.8 v2(42.6,21.25) 43.875,21.25 44.075,21.05 v1(45.35,21.05)
T_SWO: R129.1 U36.A6 U36.D12 | length 11.3
  Top Layer w0.1: v1(38.3,31.875) 38.3,31.046 38.5,30.846 38.5,29.9 38.375,29.775 U36.A6@38.375,29.375
  Top Layer w0.12: U36.D12@42.275,27.425 42.6,27.75 v1(42.6,29.975)
  Top Layer w0.2: v1(38.3,31.875) R129.1@38.3,32.55
  Signal Layer 2 w0.1: v1(38.3,31.875) 41.025,31.875 41.812,31.087 41.812,30.762 v1(42.6,29.975)
T_VCC: LNK13.2 R214.2 | length 0.6
  Top Layer w0.2: LNK13.2@33.125,16.88 R214.2@33.125,17.525
T_VCC_AIN: R213.1 R214.1 U36.N3 | length 7.4
  Top Layer w0.12: R213.1@32.05,18.425 R214.1@33.125,18.425 33.125,19.068 33.383,19.325 35.687,19.325 36.071,19.709 36.366,19.709 36.75,20.093 36.75,21.25 U36.N3@36.425,21.575
TCPP_EN: R326.1 U27.Y4 | length 137.9
  Top Layer w0.1: v1(84.025,55.425) 84.35,55.75 84.35,59.675 87.147,62.472 87.428,62.472 88.3,63.343 88.3,64.91 88,65.21 U27.Y4@88,65.6 ; R326.1@165.5,14.4 v1(166.325,14.4)
  Signal Layer 2 w0.1: v1(84.025,55.425) 84.632,55.425 84.892,55.165 87.81,55.165 88.389,54.587 94.619,54.587 97.556,51.65 97.556,49.161 100.192,46.525 101.717,45 139.75,45 141.875,42.875 147.25,42.875 151.775,38.35 151.775,12.7 157.1,7.375 163.7,7.375 166.5,10.175 166.5,11.35 167.1,11.95 167.1,13.625 v1(166.325,14.4)
TCPP_INTN: U27.W6 U50.19 | length 131.1
  Top Layer w0.09: U50.19@163.575,11.55 v1(164.375,11.55)
  Top Layer w0.1: v1(85.851,57.184) 85.42,57.615 85.42,59.82 86.075,60.475 86.2,60.6 86.2,60.705 88.722,63.227 88.722,64.601 89.31,65.189 89.31,65.72 89.6,66.01 U27.W6@89.6,66.4
  Signal Layer 2 w0.1: v1(85.851,57.184) 86.406,56.629 87.195,56.629 88.637,55.187 94.868,55.187 98.156,51.898 98.156,49.41 100.441,47.125 140.774,47.125 142.124,45.775 149.271,45.775 153.675,41.371 153.675,12.05 156.925,8.8 163.024,8.8 164.075,9.851 164.075,11.25 v1(164.375,11.55)
TOF_INT: CN4.12 U12.1 U27.J5 | length 56.2
  Top Layer w0.1: CN4.12@74.75,120.75 74.75,119.55 74.86,119.44 v1(74.86,118.937) U12.1@74.86,118.312 ; v2(88.4,74.8) U27.J5@88.8,74.4
  Bottom Layer w0.1: v1(74.86,118.937) 75.822,117.975 80.242,117.975 83.825,114.392 83.825,113.833 84.05,113.608 84.05,77.818 87.068,74.8 v2(88.4,74.8)
TOF_LPn: CN4.11 U11.1 U27.K4 | length 56.7
  Top Layer w0.1: U11.1@74.06,118.312 v1(74.06,118.937) 74.06,119.385 74.25,119.575 CN4.11@74.25,120.75 ; v2(87.6,73.2) U27.K4@88,73.6
  Bottom Layer w0.1: v1(74.06,118.937) 75.222,117.775 79.149,117.775 83.65,113.274 83.65,77.149 v2(87.6,73.2)
UART5_RX: R125.1 R155.1 U27.H3 | length 80.6
  Top Layer w0.09: 81.172,74.485 84.782,74.485 84.862,74.565 86.439,74.565 86.939,75.065 87.011,75.065 87.146,75.2 U27.H3@87.2,75.2
  Top Layer w0.1: v1(73.925,77.375) 73.907,77.375 73.925,77.357 73.925,76.908 76.348,74.485 81.172,74.485
  Top Layer w0.2: R155.1@44.1,32.15 v1(44.1,32.825) R125.1@44.1,33.5
  Bottom Layer w0.1: v1(44.1,32.825) 48.923,32.825 56.473,40.375 61.325,40.375 71.25,50.3 71.25,70.25 70.586,70.914 70.586,73.721 71.49,74.625 73.275,74.625 73.925,75.275 v1(73.925,77.375)
UART5_TX: R211.1 U27.G3 | length 92.6
  Top Layer w0.09: 82.831,75.659 82.837,75.659 ; 86.865,75.665 U27.G3@87.2,76
  Top Layer w0.1: v1(75.332,76.834) 75.981,76.834 77.176,75.639 81.172,75.639 81.182,75.649 82.821,75.649 82.831,75.659 85.38,75.659 85.401,75.68 86.126,75.68 86.141,75.665 86.865,75.665
  Top Layer w0.2: v1(42.925,16.98) R211.1@42.925,17.655
  Bottom Layer w0.1: v1(42.925,16.98) 45.855,16.98 49.21,20.335 49.21,32.829 56.556,40.175 61.408,40.175 71.45,50.217 71.45,70.333 70.791,70.992 70.791,73.636 71.58,74.425 73.358,74.425 74.825,75.892 74.825,76.327 v1(75.332,76.834)
UCPD_CC1: TP37.1 U27.T15 U50.1 | length 112.9
  Top Layer w0.09: v2(96.455,68.481) 96.468,68.481 96.787,68.8 U27.T15@96.8,68.8
  Top Layer w0.2: U50.1@162.65,12.975 162.65,14.25 TP37.1@163.15,14.75 ; TP37.1@163.153,14.753 v1(163.153,15.646)
  Signal Layer 2 w0.1: v2(96.455,68.481) 96.455,64.975 97.18,64.25 99.542,64.25 101.75,62.042 101.75,60.475 101.75,53 104.15,50.6 108.075,50.6 108.675,50 131.35,50 133.175,51.825 143.5,51.825 v1(143.75,51.575)
  Bottom Layer w0.1: v1(143.75,51.575) 144.542,51.575 152.925,43.192 152.925,22.6 155.85,19.675 157.801,19.675 160.683,16.793 162.005,16.793 v1(163.153,15.646)
UCPD_CC2: TP36.1 U27.T17 U50.3 | length 112.5
  Top Layer w0.1: v2(98,68.4) U27.T17@98.4,68.8
  Top Layer w0.2: TP36.1@161.15,16.475 162,15.625 162,14.424 161.65,14.074 U50.3@161.65,12.975 ; TP36.1@161.153,16.478 v1(161.153,17.371)
  Signal Layer 2 w0.1: v2(98,68.4) 96.645,67.044 96.645,65.054 97.259,64.44 99.621,64.44 99.811,64.25 99.825,64.25 101.925,62.15 101.925,62.136 101.95,62.111 101.95,60.475 101.95,53.083 104.233,50.8 108.158,50.8 108.758,50.2 131.267,50.2 133.092,52.025 v1(144.375,52.025)
  Bottom Layer w0.1: v1(144.375,52.025) 153.125,43.275 153.125,22.683 155.933,19.875 157.884,19.875 160.388,17.371 v1(161.153,17.371)
USART2_RX: R107.1 R134.2 U27.W15 | length 82.5
  Top Layer w0.09: U27.W15@96.8,66.4 96.8,66.138 97.305,65.633 97.305,63.626 97.165,63.486 97.165,59.915 96.938,59.688
  Top Layer w0.1: v1(96.175,49.098) 96.8,49.723 96.8,59.55 96.938,59.688
  Top Layer w0.2: R134.2@39.35,33.05 v1(39.35,33.725) R107.1@39.35,34.4
  Signal Layer 2 w0.1: v1(39.35,33.725) 41.9,33.725 52.55,33.725 58.875,40.05 73.05,40.05 82.098,49.098 83.3,49.098 v1(96.175,49.098)
USART2_TX: R154.2 U27.Y15 | length 79.3
  Top Layer w0.09: 96.689,59.889 96.975,60.175 96.975,63.595 97.115,63.735 97.115,65.285 U27.Y15@96.8,65.6
  Top Layer w0.1: R154.2@42.15,32.15 v1(42.15,34.4) ; v1(96.175,49.85) 96.525,50.2 96.525,59.725 96.689,59.889
  Signal Layer 2 w0.1: v1(42.15,34.4) 42.625,33.925 52.467,33.925 58.792,40.25 72.967,40.25 82.015,49.298 82.4,49.298 95.623,49.298 v1(96.175,49.85)
USB1CN_N: CN19.T2 U45.1 | length 3.6
  Top Layer w0.1: CN19.T2@140,14.62 140.89,15.51 140.89,17.285 140.75,17.425 U45.1@140.75,17.775
USB1CN_P: CN19.T3 U45.2 | length 3.6
  Top Layer w0.1: U45.2@141.25,17.775 141.25,17.425 141.11,17.285 141.11,15.51 CN19.T3@142,14.62
USB2CN_N: CN19.B2 U46.1 | length 8.4
  Top Layer w0.1: CN19.B2@140,12 140.34,12 140.89,12.55 140.89,12.976 141.389,13.476 142.976,13.476 143.231,13.731 143.231,16.231 143.59,16.59 143.59,17.285 143.45,17.425 U46.1@143.45,17.775
USB2CN_P: CN19.B3 U46.2 | length 8.4
  Top Layer w0.1: CN19.B3@142,12 141.66,12 141.11,12.55 141.11,12.885 141.481,13.256 143.067,13.256 143.451,13.639 143.451,16.139 143.81,16.499 143.81,17.285 143.95,17.425 U46.2@143.95,17.775
USB_DCONN_N: CN15.A7 CN15.B7 U42.2 | length 13.2
  Top Layer w0.1: U42.2@158.75,23.175 159,23.175 159.09,23.085 159.387,23.085 159.721,23.085 v1(159.986,23.35) 159.995,23.35 160.25,23.095 161.092,23.095 161.802,22.385 162.36,22.385 162.5,22.525 CN15.A7@162.7,22.525 ; v5(163.74,21.775) CN15.B7@164.4,21.775
  Bottom Layer w0.1: v1(159.986,23.35) 159.721,23.085 158.807,23.085 158.53,22.808 158.53,22.159 159.159,21.53 161.35,21.53 161.735,21.915 163.531,21.915 163.671,21.775 v5(163.74,21.775)
USB_DCONN_P: CN15.A6 CN15.B6 U42.1 | length 12.5
  Top Layer w0.1: U42.1@158.75,22.775 159,22.775 159.09,22.865 159.478,22.865 159.721,22.865 v1(159.986,22.6) 159.986,22.608 160.253,22.875 161.001,22.875 161.711,22.165 162.36,22.165 162.5,22.025 CN15.A6@162.7,22.025 ; v5(163.74,22.275) CN15.B6@164.4,22.275
  Bottom Layer w0.1: v1(159.986,22.6) 159.721,22.865 158.899,22.865 158.75,22.716 158.75,22.25 159.25,21.75 161.259,21.75 161.644,22.135 163.531,22.135 163.671,22.275 v5(163.74,22.275)
USBDN2_N: U34.3 U45.6 | length 19.5
  Top Layer w0.1: U34.3@127,28.75 127,28.25 127.14,28.11 127.14,27.049 127.834,26.355 134.759,26.355 140.89,20.224 140.89,19.565 140.75,19.425 U45.6@140.75,19.075
USBDN2_P: U34.4 U45.5 | length 19.5
  Top Layer w0.1: U34.4@127.5,28.75 127.5,28.25 127.36,28.11 127.36,27.14 127.925,26.575 134.85,26.575 141.11,20.315 141.11,19.565 141.25,19.425 U45.5@141.25,19.075
USBDN3_N: U34.6 U46.6 | length 20.5
  Top Layer w0.1: U34.6@128.5,28.75 128.5,28.25 128.64,28.11 128.64,27.685 128.95,27.375 135.439,27.375 140.914,21.9 142.133,21.9 143.59,20.443 143.59,19.875 143.59,19.565 143.45,19.425 U46.6@143.45,19.075
USBDN3_P: U34.7 U46.5 | length 20.5
  Top Layer w0.1: U34.7@129,28.75 129,28.25 128.86,28.11 128.86,27.776 129.041,27.595 135.53,27.595 141.005,22.12 142.224,22.12 143.81,20.534 143.81,19.565 143.95,19.425 U46.5@143.95,19.075
USBDR_N: U27.Y17 U42.5 | length 94.3
  Top Layer w0.1: U27.Y17@98.4,65.6 98.4,65.546 98.48,65.466 98.48,65.28 98.08,64.88 98.08,62.245 98.35,61.975 98.35,47.114 103.284,42.18 129.434,42.18 135.2,36.414 135.2,29.839 140.834,24.205 154.54,24.205 v1(154.81,23.935) ; v1(156.027,23.35) 156.292,23.085 156.523,23.085 157.36,23.085 157.45,23.175 U42.5@157.7,23.175
  Bottom Layer w0.1: v1(154.81,23.935) 155.075,24.2 156.65,24.2 156.85,24 156.85,23.535 156.4,23.085 156.292,23.085 v1(156.027,23.35)
USBDR_P: U27.W17 U42.6 | length 95.6
  Top Layer w0.1: U27.W17@98.4,66.4 98.4,66.01 98.7,65.71 98.7,65.189 98.3,64.789 98.3,62.336 98.57,62.066 98.57,47.205 103.375,42.4 129.525,42.4 135.42,36.505 135.42,29.93 140.925,24.425 154.55,24.425 v1(154.81,24.685) ; v1(156.027,22.6) 156.292,22.865 156.432,22.865 157.36,22.865 157.45,22.775 U42.6@157.7,22.775
  Bottom Layer w0.1: v1(154.81,24.685) 155.075,24.42 156.741,24.42 157.07,24.091 157.07,23.444 156.491,22.865 156.292,22.865 v1(156.027,22.6)
USBH_N: U27.AB16 U34.30 | length 52.3
  Top Layer w0.1: U27.AB16@97.6,64 97.603,63.997 97.603,63.728 97.536,63.661 97.536,46.128 102.589,41.075 115.589,41.075 122.914,33.75 v1(123.35,33.75) ; v1(123.35,32.5) U34.30@125.25,32.5
  Bottom Layer w0.1: v1(123.35,32.5) 123.35,32.525 123.68,32.855 123.68,33.42 v1(123.35,33.75)
USBH_P: U27.AA16 U34.31 | length 53.5
  Top Layer w0.1: U27.AA16@97.6,64.8 97.6,64.439 97.89,64.149 97.89,63.88 97.823,63.813 97.823,63.637 97.756,63.569 97.756,46.219 102.68,41.295 115.68,41.295 122.775,34.2 123.1,34.2 v1(123.925,34.2) ; v1(123.9,31.975) 123.925,32 U34.31@125.25,32
  Bottom Layer w0.1: v1(123.9,31.975) 123.9,34.175 v1(123.925,34.2)
VBAT: C87.2 D6.3 R30.2 U27.P7 | length 127.5
  Top Layer w0.2: v2(90.1,70.1) U27.P7@90.4,70.4
  Top Layer w0.3: D6.3@73.2,64.375 72.85,64.025 D6.3@72.825,64.025 73.075,63.775 C87.2@74.062,63.775
  Top Layer w0.4: R30.2@10.813,107.613 10.813,105.562 13.325,103.05 17.2,103.05 18.4,104.25 24.85,104.25 29.975,99.125 v1(43,99.125)
  Top Layer w0.45: D6.3@73.2,64.375 v1(73.2,65.331)
  Signal Layer 3 w0.45: v1(43,99.125) v1(73.8,99.125) ; v1(73.2,65.331) 73.2,65.625 73.6,66.025 76.3,66.025 77.4,67.125 83.383,67.125 83.908,67.65 84.15,67.65 86.6,70.1 v2(90.1,70.1)
  Bottom Layer w0.45: v1(73.2,65.331) 73.2,68.874 74.075,69.749 74.075,73.175 76.675,75.775 76.675,77.25 74.45,79.475 74.45,90.525 74.6,90.675 74.6,98.325 v1(73.8,99.125)
VBUS_DIV: R219.1 R220.2 TP35.1 U27.AA6 | length 113.9
  Top Layer w0.1: v1(85.851,56.429) 86.62,57.198 86.62,60.475 86.62,60.589 89.102,63.07 89.102,64.302 U27.AA6@89.6,64.8
  Top Layer w0.2: v1(153.075,19.275) 153.096,19.275 155.171,17.2 TP35.1@155.193,17.2
  Top Layer w0.3: TP35.1@155.193,17.2 155.196,17.197 155.958,17.197 156.675,16.48 157.32,16.48 R220.2@157.325,16.475 R219.1@158.4,16.475
  Signal Layer 2 w0.1: v1(85.851,56.429) 87.112,56.429 88.555,54.987 94.785,54.987 97.956,51.816 97.956,49.327 100.358,46.925 140.691,46.925 142.041,45.575 149.189,45.575 153.475,41.289 153.475,19.669 153.081,19.275 v1(153.075,19.275)
VBUS_HOST_EN: R323.2 U34.16 U41.3 | length 16.1
  Top Layer w0.1: U34.16@130.75,32.5 131.925,32.5 v1(132.375,32.95)
  Top Layer w0.3: v1(129.16,22.9) U41.3@129.16,24.15
  Signal Layer 2 w0.15: v1(129.16,22.9) 130.544,22.9 132.4,24.757 132.4,32.925 v1(132.375,32.95)
  Bottom Layer w0.3: v1(129.16,22.9) R323.2@129.16,23.775
VBUS_HOST_EN2: R324.2 U34.18 U41.4 | length 16.9
  Top Layer w0.15: U34.18@130.75,33.5 v1(131.6,33.5)
  Top Layer w0.3: v1(127.89,22.9) U41.4@127.89,24.15
  Signal Layer 2 w0.15: v1(127.89,22.9) 128.415,23.425 130.715,23.425 132.15,24.86 132.15,32.246 131.6,32.796 v1(131.6,33.5)
  Bottom Layer w0.3: v1(127.89,22.9) R324.2@127.89,23.775
VBUS_HOST_FAULT2n: U34.19 U41.5 | length 20.6
  Top Layer w0.2: U34.19@130,34.25 v1(130.55,34.25)
  Top Layer w0.3: v1(127.89,18.15) U41.5@127.89,19.4
  Signal Layer 2 w0.2: v1(127.89,18.15) 127.89,20.98 127.22,21.65 127.22,23.58 127.865,24.225 129.635,24.225 130.55,25.14 v1(130.55,34.25)
VBUS_HOST_FAULTn: U34.17 U41.8 | length 17
  Top Layer w0.1: U34.17@130.75,33 131.701,33 132.025,33.324 132.025,33.364 v1(132.37,33.709)
  Top Layer w0.3: U41.8@131.7,19.4 v1(131.7,20.65)
  Signal Layer 2 w0.15: v1(131.7,20.65) 131.7,22 132.925,23.225 132.925,33.154 v1(132.37,33.709)
VBUS_STLK: C164.1 C166.2 C172.2 CN21.A4 CN21.A9 CN21.B4 CN21.B9 D3.1 U48.1 U49.5 U52.3 U52.4 | length 58.6
  Top Layer w0.3: U52.3@32.625,5.65 33.149,5.65 33.325,5.826 33.325,6.15 U52.4@32.625,6.15 ; C164.1@38.25,12.7 C164.1@38.262,12.688 ; U48.1@39.488,12.688 U48.1@39.5,12.675 ; CN21.B9@40.665,7.61 40.665,8.244 40.915,8.494 v1(40.915,8.535) v1(40.915,10.063) ; CN21.B4@43.165,7.61 43.165,8.244 43.415,8.494 v1(43.415,8.535) CN21.A9@43.415,9.31 v1(43.415,10.063)
  Top Layer w0.55: U48.1@39.5,12.675 39.63,12.675 39.63,12.014 40.019,11.625 40.915,10.729 v1(40.915,10.063)
  Top Layer w0.8: D3.1@30.22,36.025 28.05,36.025 25.35,33.325 25.35,19.95 30.63,14.67 36.351,14.67 36.82,14.201 v1(36.82,13.325) ; 33.325,6.15 C172.2@34.025,6.15 34.025,6.75 35.8,8.525 35.8,8.875 37.445,10.52 v1(37.445,12.7) ; U49.5@34.125,13.325 C166.2@35.6,13.325 v1(36.82,13.325) ; C164.1@38.25,12.7 v1(37.445,12.7) ; C164.1@38.262,12.688 U48.1@39.488,12.688 ; v1(36.82,13.325) v1(37.445,12.7)
  other v1: 37.445,11.327 37.445,12.014
VBUSc: C156.2 C159.2 CN15.A4 CN15.A9 CN15.B4 CN15.B9 R219.2 R225.1 R232.1 TP39.1 U43.1 U50.9 | length 25.6
  Top Layer w0.2: v1(159.075,6.845) R232.1@159.75,6.845
  Top Layer w0.3: R225.1@158.25,10.975 158.43,10.975 158.855,10.55 U50.9@159.725,10.55 ; C159.2@159.3,17.875 C159.2@159.275,17.9 C159.2@159.3,17.925 ; C156.2@159.3,19.25 C156.2@159.312,19.263 ; U43.1@159.312,20.488 U43.1@159.325,20.5 ; v1(161.947,23.525) CN15.A9@162.7,23.525 v1(163.475,23.525) 163.516,23.525 163.766,23.275 CN15.B4@164.4,23.275 ; v1(161.972,20.937) 162.04,20.937 162.128,21.025 CN15.A4@162.7,21.025 163.641,21.025 163.891,20.775 CN15.B9@164.4,20.775
  Top Layer w0.55: C159.2@159.3,17.925 C156.2@159.3,19.25 ; C156.2@159.312,19.263 U43.1@159.312,20.488 ; U43.1@159.325,20.5 159.325,20.65 161.685,20.65 v1(161.972,20.937)
  Top Layer w0.8: R225.1@158.25,10.975 TP39.1@158.25,13.345 159.3,14.395 C159.2@159.3,17.875
  Bottom Layer w0.3: v1(158.25,11.75) 158.25,7.67 v1(159.075,6.845)
  other v1: 158.25,12.4 163.59,21.025
VDD3V3_USB: C61.2 R286.1 U26.13 | length 74.4
  Top Layer w0.21: U26.13@49.9,75.457 49.9,75.027 50.363,74.565 50.618,74.565 50.62,74.562 50.69,74.562 50.825,74.427 C61.2@50.825,74.357
  Top Layer w0.3: C61.2@50.825,74.357 v3(51.435,74.357)
  Signal Layer 3 w0.5: v3(51.435,74.357) 52.55,73.242 52.55,72.525 56.888,68.187 61.437,68.187 62.125,67.5 62.125,62.95 ; v1(99.5,54.1) 83.825,54.1 79.05,58.875 79.05,60.35 78.475,60.925 64.15,60.925 62.963,62.112 ; 62.125,62.95 62.963,62.112 ; 62.125,62.95 62.963,62.112
  Bottom Layer w0.3: R286.1@97.725,63.575 97.725,62.825 97.35,62.45 97.35,60.475 97.35,58.387 98.35,57.387 98.35,55.25 v1(99.5,54.1)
